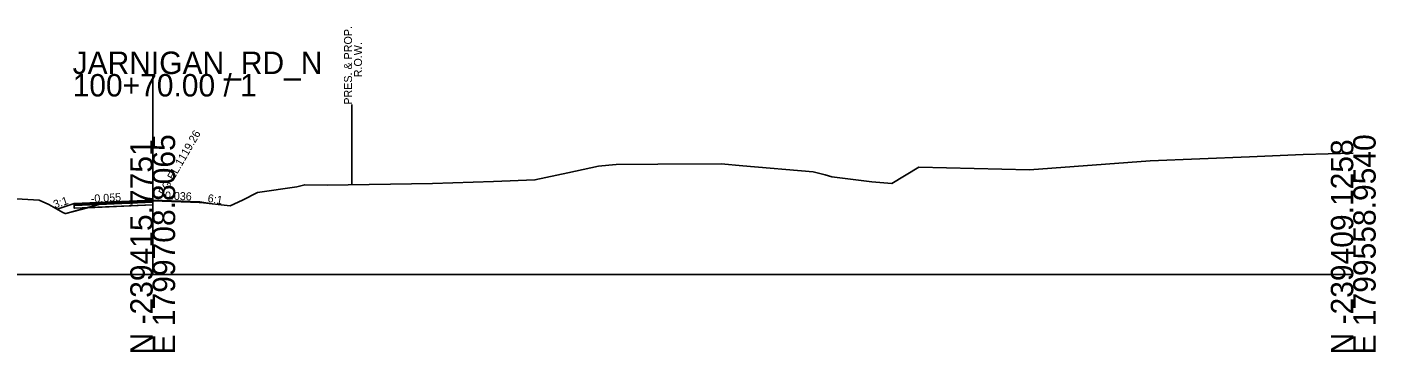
# Model space of a CAD drawing. Extents: x 214513 to 217151, y 214739 to 216780.
# Drawn here: x 214882.7 to 215051.2, y 215738.7 to 215779.2 of the extents above; entities that cross this region are included whole.
import ezdxf

# ---------------------------------------------------------------- set-up
doc = ezdxf.new("R2010")
doc.units = 0
for name, color, linetype in [('CONCEPT - TRANSPORTATION - Roads Text', 7, 'Continuous'), ('DESIGN - CENTERLINE - Proposed Text', 7, 'Continuous'), ('DESIGN - DRAINAGE - Special Ditches', 7, 'Continuous'), ('DESIGN - EARTHWORK - Shapes', 7, 'Continuous'), ('DESIGN - TRANSPORTATION - Text', 7, 'Continuous'), ('DESIGN - TYPICAL - Slope Tie Text', 7, 'Continuous'), ('SURVEY - DTM GRAPHICS - Triangles', 7, 'Continuous'), ('SURVEY - PROPERTY - ROW Lines', 7, 'Continuous'), ('XSCell', 7, 'Continuous')]:
    doc.layers.add(name, color=color, linetype=linetype)

msp = doc.modelspace()

# ---------------------------------------------------------------- linework, layer by layer
at = {"layer": 'DESIGN - DRAINAGE - Special Ditches'}
for points in [[(214888.56, 215757.19), (214886.44, 215756.48)], [(214888.56, 215757.19), (214898.36, 215757.62), (214898.36, 215757.52), (214898.36, 215757.52), (214888.56, 215757.09), (214888.56, 215757.09), (214888.56, 215757.09), (214888.56, 215757.19), (214888.56, 215757.19)], [(214888.56, 215757.09), (214898.36, 215757.52), (214898.36, 215757.37), (214898.36, 215757.37), (214888.56, 215756.94), (214888.56, 215756.94), (214888.56, 215756.94), (214888.56, 215757.09), (214888.56, 215757.09)], [(214888.56, 215756.94), (214888.56, 215756.94), (214888.56, 215756.61), (214888.56, 215756.61), (214888.56, 215756.61), (214898.36, 215757.04), (214898.36, 215757.04), (214898.36, 215757.37), (214888.56, 215756.94)], [(214898.36, 215757.62), (214898.36, 215757.62), (214898.36, 215757.52), (214898.36, 215757.52), (214898.36, 215757.52), (214904.26, 215757.31), (214904.26, 215757.31), (214904.26, 215757.41), (214898.36, 215757.62)], [(214904.26, 215757.41), (214905.81, 215757.15)]]:
    msp.add_lwpolyline(points, dxfattribs=at)
at = {"layer": 'DESIGN - EARTHWORK - Shapes'}
for p, q in [((214888.56, 215757.19), (214886.44, 215756.48)), ((214888.56, 215757.09), (214888.56, 215757.19)), ((214888.56, 215756.94), (214888.56, 215757.09)), ((214888.56, 215756.61), (214888.56, 215756.94)), ((214890.22, 215756.68), (214888.56, 215756.61)), ((214891.64, 215757.08), (214890.22, 215756.68)), ((214898.36, 215757.37), (214891.64, 215757.08)), ((214891.64, 215757.08), (214898.36, 215757.37)), ((214892.29, 215757.26), (214891.64, 215757.08)), ((214894.35, 215757.35), (214892.29, 215757.26)), ((214898.36, 215757.51), (214894.35, 215757.35)), ((214898.36, 215757.52), (214898.36, 215757.51)), ((214898.36, 215757.51), (214898.6, 215757.52)), ((214898.6, 215757.52), (214898.36, 215757.52)), ((214898.36, 215757.37), (214898.36, 215757.51)), ((214904.26, 215757.41), (214904.26, 215757.32)), ((214905.81, 215757.15), (214904.26, 215757.41))]:
    msp.add_line(p, q, dxfattribs=at)
for points in [[(214886.44, 215756.48), (214887.12, 215756.09), (214887.44, 215755.94), (214887.48, 215755.92), (214887.52, 215755.94), (214890.22, 215756.68)], [(214890.22, 215756.68), (214898.36, 215757.04), (214898.36, 215757.37)], [(214904.26, 215757.32), (214904.18, 215757.33), (214898.74, 215757.52), (214898.6, 215757.52)], [(214898.6, 215757.52), (214904.26, 215757.31), (214904.26, 215757.32)], [(214904.26, 215757.32), (214904.32, 215757.32), (214905.81, 215757.15)]]:
    msp.add_lwpolyline(points, dxfattribs=at)
at = {"layer": 'SURVEY - DTM GRAPHICS - Triangles'}
msp.add_lwpolyline([(214879.94, 215757.86), (214884.17, 215757.64), (214885.38, 215757.09), (214887.12, 215756.09), (214887.44, 215755.94), (214887.48, 215755.92), (214887.52, 215755.94), (214892.35, 215757.27), (214892.87, 215757.29), (214898.74, 215757.52), (214904.18, 215757.33), (214904.26, 215757.32), (214904.32, 215757.32), (214908.02, 215756.91), (214909.56, 215757.61), (214911.46, 215758.57), (214916.38, 215759.29), (214917.36, 215759.55), (214920.17, 215759.5), (214933.3, 215759.69), (214940.93, 215759.96), (214946.12, 215760.15), (214950.24, 215761.04), (214954.06, 215761.88), (214955.36, 215761.99), (214956.28, 215762.07), (214961.49, 215762.1), (214969.37, 215762.15), (214972.11, 215761.92), (214980.89, 215761.15), (214982.36, 215760.78), (214983.22, 215760.54), (214988.21, 215759.91), (214990.72, 215759.68), (214994.1, 215761.75), (214994.1, 215761.75), (214994.1, 215761.75), (215007.91, 215761.4), (215022.99, 215762.51), (215035.4, 215763.04), (215042.09, 215763.31), (215048.36, 215763.49)], dxfattribs=at)
at = {"layer": 'SURVEY - PROPERTY - ROW Lines'}
msp.add_lwpolyline([(214923.26, 215769.54), (214923.26, 215759.54)], dxfattribs=at)
at = {"layer": 'XSCell'}
for p, q in [((214898.36, 215748.36), (214898.36, 215773.36)), ((214748.36, 215748.36), (214898.36, 215748.36)), ((214898.36, 215748.36), (215048.36, 215748.36))]:
    msp.add_line(p, q, dxfattribs=at)

# ---------------------------------------------------------------- texts
at = {"layer": 'CONCEPT - TRANSPORTATION - Roads Text'}
for s, rotation, p in [('-0.055', 3.121, (214890.65, 215757.3)), ('-0.036', 357.925, (214899.43, 215757.72))]:
    msp.add_text(s, height=1, rotation=rotation, dxfattribs=at).set_placement(p)
at = {"layer": 'DESIGN - CENTERLINE - Proposed Text'}
msp.add_text('FG EL.1119.26', height=1, rotation=60, dxfattribs=at).set_placement((214899.86, 215758.12))
at = {"layer": 'DESIGN - TRANSPORTATION - Text'}
for s, p in [('PRES. & PROP. ', (214923.26, 215769.54)), ('R.O.W.', (214924.51, 215772.96))]:
    msp.add_text(s, height=1, rotation=90, dxfattribs=at).set_placement(p)
at = {"layer": 'DESIGN - TYPICAL - Slope Tie Text'}
for s, rotation, p in [('3:1', 18.4349, (214886.14, 215756.58)), ('6:1', 350.5377, (214905.17, 215757.41))]:
    msp.add_text(s, height=1, rotation=rotation, dxfattribs=at).set_placement(p)
at = {"layer": 'XSCell'}
for s, p in [('JARNIGAN_RD_N', (214888.36, 215773.36)), ('100+70.00 / 1', (214888.36, 215770.56))]:
    msp.add_text(s, height=2.8, dxfattribs=at).set_placement(p)
for s, p in [('N -239415.7751', (214898.36, 215738.36)), ('E 1799708.8065', (214901.16, 215738.36)), ('N -239409.1258', (215048.36, 215738.36)), ('E 1799558.9540', (215051.16, 215738.36))]:
    msp.add_text(s, height=2.8, rotation=90, dxfattribs=at).set_placement(p)

doc.saveas('drawing.dxf')
